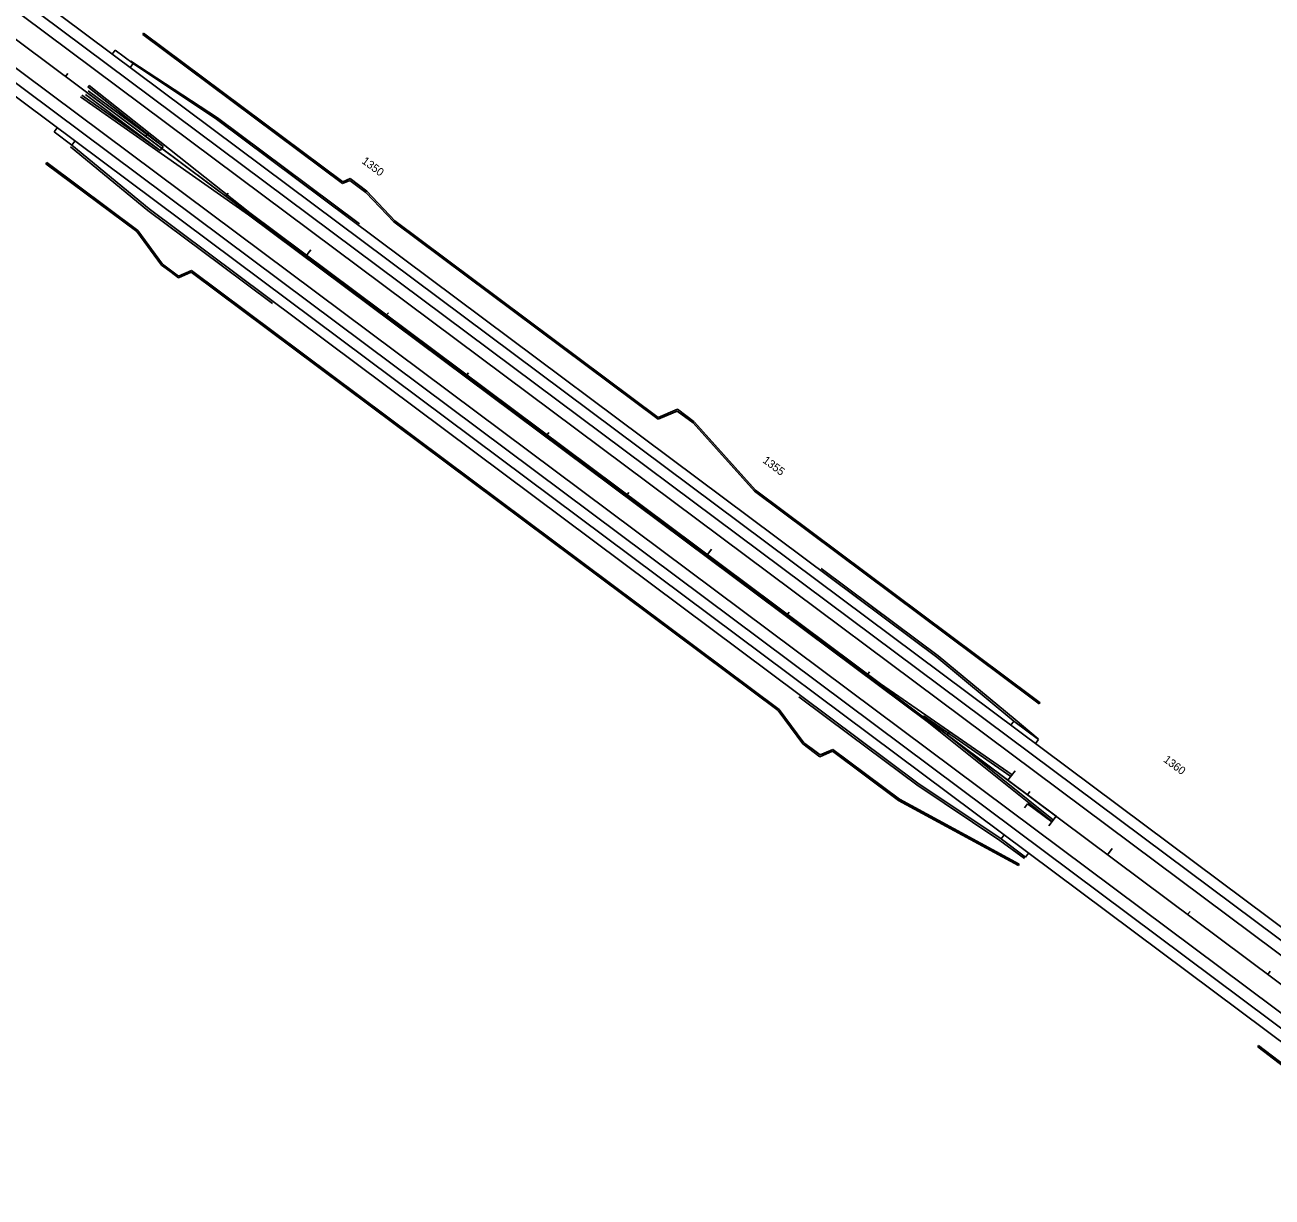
# Model space of a CAD drawing. Extents: x 2339272 to 2351734, y 366540 to 375057.
# Drawn here: x 2342189 to 2343436, y 371714 to 372885 of the extents above; entities that cross this region are included whole.
import ezdxf

# ---------------------------------------------------------------- set-up
doc = ezdxf.new("R2010")
doc.units = 0
for name, color, linetype in [('RD_HC_Cl', 7, 'Continuous'), ('RD_HC_Data_Tic', 7, 'Continuous'), ('RD_HC_TX_Sta50', 7, 'Continuous'), ('RD_PD_Bridge', 7, 'Continuous'), ('RD_PD_Final_LnLine', 7, 'Continuous'), ('RD_PD_Final_TrvlWay', 7, 'Continuous'), ('RD_PD_GrRail', 7, 'Continuous'), ('RD_PD_MedBWall', 7, 'Continuous'), ('RD_PD_NOISE-WALL-GM', 7, 'Continuous'), ('RD_PD_PaveShd', 7, 'Continuous')]:
    doc.layers.add(name, color=color, linetype=linetype)

msp = doc.modelspace()

# ---------------------------------------------------------------- linework, layer by layer
at = {"layer": 'RD_HC_Cl'}
msp.add_line((2339299.7, 375020.3), (2345298.7, 370542.8), dxfattribs=at)
at = {"layer": 'RD_HC_Data_Tic'}
for p, q in [((2342229.4, 372833.7), (2342231.8, 372836.9)), ((2342309.5, 372773.9), (2342311.9, 372777.1)), ((2342389.7, 372714.1), (2342392.1, 372717.3)), ((2342469.8, 372654.3), (2342474.6, 372660.7)), ((2342549.9, 372594.5), (2342552.3, 372597.7)), ((2342630.1, 372534.6), (2342632.5, 372537.8)), ((2342710.2, 372474.8), (2342712.6, 372478)), ((2342790.4, 372415), (2342792.8, 372418.2)), ((2342870.5, 372355.2), (2342875.3, 372361.6)), ((2342950.6, 372295.4), (2342953, 372298.6)), ((2343030.8, 372235.6), (2343033.2, 372238.8)), ((2343110.9, 372175.8), (2343113.3, 372179)), ((2343191.1, 372115.9), (2343193.5, 372119.2)), ((2343271.2, 372056.1), (2343276, 372062.5)), ((2343351.3, 371996.3), (2343353.7, 371999.5)), ((2343431.5, 371936.5), (2343433.9, 371939.7))]:
    msp.add_line(p, q, dxfattribs=at)
at = {"layer": 'RD_PD_Bridge'}
for p, q in [((2342276.3, 372856.1), (2342279.3, 372860.1)), ((2342297.1, 372846.8), (2342279.3, 372860.1)), ((2342294.1, 372842.8), (2342297.1, 372846.8)), ((2342221.1, 372782.5), (2342218.1, 372778.5)), ((2342218.1, 372778.5), (2342235.9, 372765.2)), ((2342238.9, 372769.2), (2342235.9, 372765.2)), ((2343174.7, 372185.5), (2343177.7, 372189.5)), ((2343202.2, 372171.3), (2343177.7, 372189.5)), ((2343199.2, 372167.3), (2343202.2, 372171.3)), ((2343188.2, 372103.1), (2343191.2, 372107.1)), ((2343191.2, 372107.1), (2343215.6, 372088.9)), ((2343167.8, 372075.9), (2343164.8, 372071.9)), ((2343164.8, 372071.9), (2343189.3, 372053.6)), ((2343192.3, 372057.6), (2343189.3, 372053.6))]:
    msp.add_line(p, q, dxfattribs=at)
at = {"layer": 'RD_PD_Final_LnLine'}
for p, q in [((2343504.5, 371925.7), (2339320.6, 375048.4)), ((2343497.3, 371916.1), (2339313.4, 375038.8)), ((2339285.9, 375001.9), (2343469.8, 371879.2)), ((2339278.7, 374992.3), (2343462.6, 371869.6))]:
    msp.add_line(p, q, dxfattribs=at)
at = {"layer": 'RD_PD_Final_TrvlWay'}
for p, q in [((2343458.6, 371973.7), (2339327.2, 375057.2)), ((2339272.2, 374983.5), (2343456.1, 371860.8)), ((2343432.2, 371878.8), (2343432.1, 371878.9))]:
    msp.add_line(p, q, dxfattribs=at)
at = {"layer": 'RD_PD_GrRail'}
for p, q in [((2342294.7, 372849.1), (2342381.5, 372792.6)), ((2342381.5, 372792.6), (2342472.2, 372724.8)), ((2342311.8, 372699.8), (2342234.6, 372763.6)), ((2342472.2, 372724.8), (2342523.5, 372686.6)), ((2342385.1, 372645.1), (2342311.9, 372699.8)), ((2342436.3, 372606.9), (2342385.1, 372645.1)), ((2342985.1, 372342.1), (2343036.4, 372303.8)), ((2343036.4, 372303.8), (2343101.8, 372255)), ((2343101.8, 372255), (2343179, 372191.1)), ((2343014, 372175.7), (2342962.7, 372214)), ((2343179, 372191.1), (2343202, 372171.9)), ((2343080.5, 372126.1), (2343014, 372175.7)), ((2343163.7, 372070.2), (2343080.6, 372126)), ((2343188.3, 372052.4), (2343163.7, 372070.2))]:
    msp.add_line(p, q, dxfattribs=at)
at = {"layer": 'RD_PD_MedBWall'}
for p, q in [((2342244.5, 372813.5), (2342412.3, 372695.7)), ((2342245.7, 372815.2), (2342324.3, 372759.9)), ((2342251.9, 372823.3), (2342253.1, 372824.9)), ((2342251.9, 372823.3), (2342327.1, 372763.7)), ((2342253.1, 372824.9), (2342413.7, 372697.6)), ((2342327.1, 372763.7), (2342325.7, 372761.8)), ((2342324.3, 372759.9), (2342325.7, 372761.8)), ((2342412.3, 372695.7), (2343090.8, 372189.3)), ((2342413.7, 372697.6), (2343044.2, 372227)), ((2343175.8, 372135.8), (2343044.2, 372227)), ((2343087.1, 372194.9), (2343217.1, 372090.8)), ((2343174.6, 372134.2), (2343087.1, 372194.9)), ((2343090.8, 372189.3), (2343215.8, 372089.2)), ((2343217.1, 372090.8), (2343215.8, 372089.2)), ((2343216, 372089.5), (2343217.3, 372091.1))]:
    msp.add_line(p, q, dxfattribs=at)
at = {"layer": 'RD_PD_NOISE-WALL-GM'}
for p, q in [((2342307.6, 372877), (2342306.7, 372875.8)), ((2342307.6, 372877), (2342506.6, 372728.5)), ((2342306.7, 372875.8), (2342506.4, 372726.8)), ((2342210.7, 372747.8), (2342209.8, 372746.6)), ((2342209.8, 372746.6), (2342300.7, 372678.8)), ((2342210.7, 372747.8), (2342301.7, 372679.9)), ((2342506.4, 372726.8), (2342513.8, 372730)), ((2342506.6, 372728.5), (2342514, 372731.7)), ((2342513.8, 372730), (2342521.8, 372724)), ((2342514, 372731.7), (2342530.9, 372719.1)), ((2342529.9, 372718), (2342521.8, 372724)), ((2342529.9, 372718), (2342557.7, 372688.5)), ((2342530.9, 372719.1), (2342558.8, 372689.5)), ((2342558.6, 372689.7), (2342822.1, 372493)), ((2342300.7, 372678.8), (2342325.5, 372645.3)), ((2342301.7, 372679.9), (2342326.6, 372646.3)), ((2342557.7, 372688.5), (2342821.9, 372491.3)), ((2342325.5, 372645.3), (2342333.7, 372639.2)), ((2342326.6, 372646.3), (2342334.6, 372640.4)), ((2342342.4, 372632.7), (2342333.7, 372639.2)), ((2342342.6, 372634.4), (2342334.6, 372640.4)), ((2342355.4, 372639.8), (2342342.6, 372634.4)), ((2342355.4, 372639.8), (2342942.9, 372201.4)), ((2342355.2, 372638.1), (2342342.4, 372632.7)), ((2342355.2, 372638.1), (2342941.8, 372200.3)), ((2342821.9, 372491.3), (2342841, 372499.5)), ((2342822.1, 372493), (2342841.2, 372501.3)), ((2342841, 372499.5), (2342857, 372487.6)), ((2342841.2, 372501.3), (2342857.9, 372488.8)), ((2342857, 372487.6), (2342918.3, 372419.3)), ((2342858.2, 372488.5), (2342919.2, 372420.5)), ((2342918.3, 372419.3), (2343195, 372212.8)), ((2342919.2, 372420.5), (2343195.9, 372214)), ((2343203, 372206.8), (2343195, 372212.8)), ((2343203.9, 372208), (2343195.9, 372214)), ((2343203.9, 372208), (2343203, 372206.8)), ((2342941.8, 372200.3), (2342966.7, 372166.8)), ((2342942.9, 372201.4), (2342967.7, 372167.8)), ((2342966.7, 372166.8), (2342983.6, 372154.1)), ((2342967.7, 372167.8), (2342975.8, 372161.8)), ((2343110.9, 372175.8), (2343110.9, 372175.8)), ((2342983.8, 372155.9), (2342975.8, 372161.8)), ((2342996.3, 372159.6), (2342983.6, 372154.1)), ((2342996.5, 372161.3), (2342983.8, 372155.9)), ((2342996.3, 372159.6), (2343062.2, 372110.4)), ((2342996.5, 372161.3), (2343063.1, 372111.6)), ((2343062.4, 372110.3), (2343182.3, 372045.3)), ((2343063.1, 372111.6), (2343183, 372046.7)), ((2343183, 372046.7), (2343182.3, 372045.3)), ((2343422.3, 371865.6), (2343421.4, 371864.3)), ((2343421.4, 371864.3), (2343522.5, 371786.4)), ((2343422.3, 371865.6), (2343524.1, 371787.1))]:
    msp.add_line(p, q, dxfattribs=at)
at = {"layer": 'RD_PD_PaveShd'}
for p, q in [((2342297.1, 372846.8), (2342380.3, 372791)), ((2342249.4, 372815.9), (2342324.3, 372759.9)), ((2342250.8, 372817.8), (2343219.8, 372094.5)), ((2342252.1, 372819.6), (2342327.1, 372763.7)), ((2342246.4, 372812.1), (2342254.7, 372806)), ((2343100.6, 372253.4), (2342380.3, 372791)), ((2342313.1, 372701.4), (2342235.9, 372765.2)), ((2342313.1, 372701.4), (2343081.7, 372127.7)), ((2343100.6, 372253.4), (2343177.7, 372189.5)), ((2343178.8, 372140.1), (2343171.6, 372130.5)), ((2343081.7, 372127.7), (2343164.8, 372071.9)), ((2343212.6, 372084.9), (2343219.8, 372094.5))]:
    msp.add_line(p, q, dxfattribs=at)

# ---------------------------------------------------------------- texts
at = {"layer": 'RD_HC_TX_Sta50'}
for s, p in [('1350', (2342525, 372747.8)), ('1355', (2342925.8, 372448.7)), ('1360', (2343326.4, 372149.7))]:
    msp.add_text(s, height=8, rotation=323.2637, dxfattribs=at).set_placement(p)

doc.saveas('drawing.dxf')
